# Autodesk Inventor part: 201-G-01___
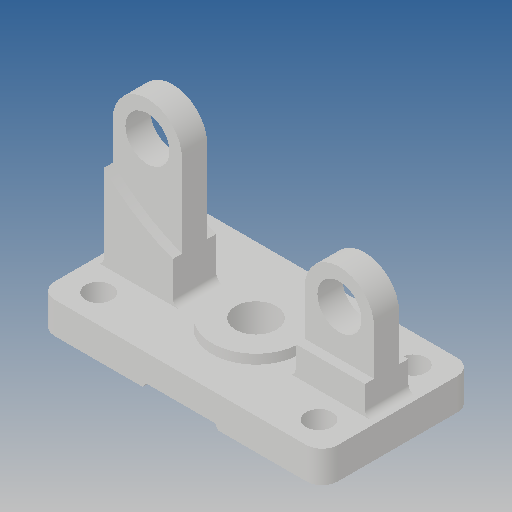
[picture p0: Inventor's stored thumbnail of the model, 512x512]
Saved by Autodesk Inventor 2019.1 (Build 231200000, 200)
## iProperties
Created: 2010-06
Part Number: 201-G-01___
Material: Ogólny
Document SubType Name: Modeling
Designer: CADENGINEERING4
Density: 1 g/cm^3
Appearance: Domyślna
Author: CADENGINEERING4
Revision Number: ANY
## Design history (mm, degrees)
feature "NONE"
node "Bryła1"
